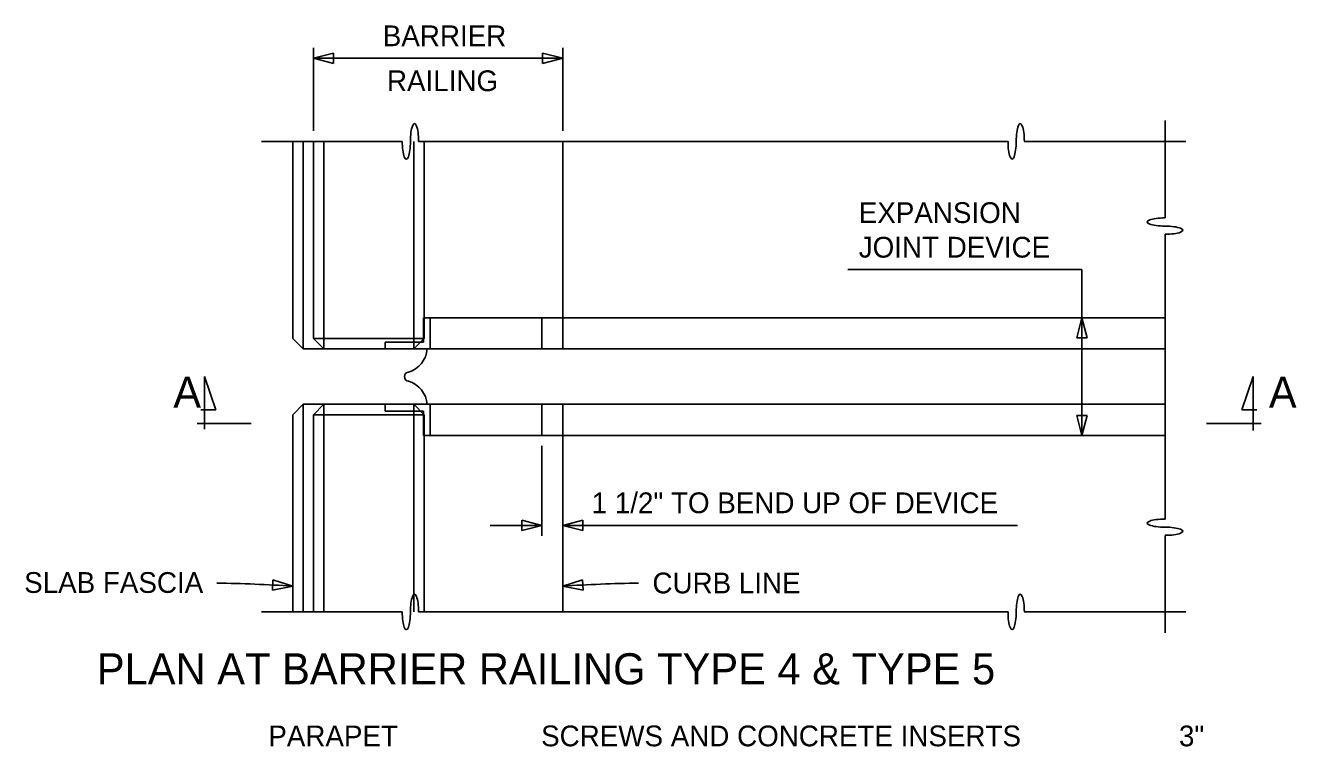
# Model space of a CAD drawing. Extents: x 19590 to 20151, y 19944 to 20103.
# Drawn here: x 19615.96 to 19644.51, y 20079.43 to 20095.63 of the extents above; entities that cross this region are included whole.
import ezdxf

# ---------------------------------------------------------------- set-up
doc = ezdxf.new("R2010")
doc.units = 0
for name, color, linetype in [('DETAIL_PR', 7, 'Continuous'), ('DETAIL_TEXT_DIMEN_PR', 7, 'Continuous'), ('Level 1', 7, 'Continuous')]:
    doc.layers.add(name, color=color, linetype=linetype)

msp = doc.modelspace()

# ---------------------------------------------------------------- linework, layer by layer
at = {"layer": 'DETAIL_PR'}
for p, q in [((19641.559, 20093.494), (19641.559, 20091.306)), ((19621.266, 20093.028), (19624.426, 20093.028)), ((19621.965, 20093.028), (19621.965, 20088.596)), ((19622.199, 20093.028), (19622.199, 20088.363)), ((19622.432, 20093.028), (19622.432, 20088.596)), ((19622.665, 20093.028), (19622.665, 20088.363)), ((19624.687, 20093.028), (19624.687, 20088.363)), ((19624.793, 20093.028), (19638.033, 20093.028)), ((19624.92, 20093.028), (19624.92, 20088.596)), ((19628.03, 20093.028), (19628.03, 20088.363)), ((19638.399, 20093.028), (19642.026, 20093.028)), ((19641.559, 20090.939), (19641.559, 20086.263)), ((19624.901, 20088.518), (19624.901, 20089.063)), ((19624.901, 20089.063), (19628.03, 20089.063)), ((19625.056, 20088.363), (19625.056, 20089.063)), ((19627.564, 20088.363), (19627.564, 20089.063)), ((19628.03, 20089.062), (19641.559, 20089.062)), ((19622.199, 20088.363), (19621.966, 20088.596)), ((19622.432, 20088.596), (19624.92, 20088.596)), ((19622.432, 20088.596), (19622.665, 20088.363)), ((19624.045, 20088.363), (19624.045, 20088.518)), ((19624.045, 20088.518), (19624.901, 20088.518)), ((19624.92, 20088.596), (19624.687, 20088.363)), ((19622.199, 20088.363), (19624.045, 20088.363)), ((19624.045, 20088.363), (19641.559, 20088.363)), ((19622.199, 20087.119), (19621.966, 20086.886)), ((19622.199, 20087.119), (19624.045, 20087.119)), ((19622.199, 20082.453), (19622.199, 20087.119)), ((19622.432, 20086.886), (19622.665, 20087.119)), ((19622.665, 20082.453), (19622.665, 20087.119)), ((19624.045, 20087.119), (19624.045, 20086.963)), ((19624.045, 20087.119), (19641.559, 20087.119)), ((19624.045, 20086.963), (19624.901, 20086.963)), ((19624.687, 20082.453), (19624.687, 20087.119)), ((19624.92, 20086.885), (19624.687, 20087.119)), ((19624.901, 20086.963), (19624.901, 20086.419)), ((19625.056, 20087.119), (19625.056, 20086.419)), ((19627.564, 20086.419), (19627.564, 20087.119)), ((19628.03, 20082.453), (19628.03, 20087.119)), ((19621.965, 20082.453), (19621.965, 20086.885)), ((19622.432, 20082.453), (19622.432, 20086.885)), ((19622.432, 20086.885), (19624.92, 20086.885)), ((19624.92, 20082.453), (19624.92, 20086.885)), ((19624.901, 20086.419), (19628.03, 20086.419)), ((19628.03, 20086.419), (19641.559, 20086.419)), ((19641.559, 20084.542), (19641.559, 20086.263)), ((19641.559, 20084.175), (19641.559, 20081.987)), ((19621.266, 20082.454), (19624.426, 20082.454)), ((19624.793, 20082.454), (19638.033, 20082.454)), ((19638.399, 20082.454), (19642.026, 20082.454))]:
    msp.add_line(p, q, dxfattribs=at)
for centre, radius, start, end in [((19624.374, 20088.428), 0.618, 288.1365, 353.9316), ((19624.574, 20087.741), 0.101, 94.4387, 265.5613), ((19624.374, 20087.053), 0.618, 6.0684, 71.8635)]:
    msp.add_arc(centre, radius, start, end, dxfattribs=at)
for centre, major_axis, ratio, start_param, end_param in [((19624.701, 20093.028), (0, -0.398), 0.230204, 1.570796, 4.712389), ((19638.308, 20093.028), (0, -0.398), 0.230204, 1.570796, 4.712389), ((19624.517, 20093.028), (0, -0.398), 0.230206, 4.712389, 7.853982), ((19638.124, 20093.028), (0, -0.398), 0.230206, 4.712389, 7.853982), ((19641.559, 20091.215), (0.398, 0), 0.230204, 1.570796, 4.712389), ((19641.559, 20091.031), (0.398, 0), 0.230206, 4.712389, 7.853982), ((19641.559, 20084.45), (0.398, 0), 0.230204, 1.570796, 4.712389), ((19641.559, 20084.267), (0.398, 0), 0.230206, 4.712389, 7.853982), ((19624.701, 20082.454), (0, -0.398), 0.230204, 1.570796, 4.712389), ((19638.308, 20082.454), (0, -0.398), 0.230204, 1.570796, 4.712389), ((19624.517, 20082.454), (0, -0.398), 0.230206, 4.712389, 7.853982), ((19638.124, 20082.454), (0, -0.398), 0.230206, 4.712389, 7.853982)]:
    msp.add_ellipse(centre, major_axis=major_axis, ratio=ratio, start_param=start_param, end_param=end_param, dxfattribs=at)
at = {"layer": 'DETAIL_TEXT_DIMEN_PR'}
for p, q in [((19622.432, 20093.261), (19622.432, 20095.127)), ((19622.884, 20095.011), (19622.432, 20094.894)), ((19622.884, 20094.777), (19622.884, 20095.011)), ((19627.579, 20095.011), (19628.03, 20094.894)), ((19627.579, 20094.777), (19627.579, 20095.011)), ((19628.03, 20093.261), (19628.03, 20095.127)), ((19622.432, 20094.894), (19628.03, 20094.894)), ((19622.432, 20094.894), (19622.884, 20094.777)), ((19628.03, 20094.894), (19627.579, 20094.777)), ((19634.436, 20090.151), (19639.693, 20090.151)), ((19639.693, 20090.151), (19639.693, 20086.419)), ((19619.984, 20086.56), (19619.983, 20087.741)), ((19619.983, 20087.741), (19620.238, 20086.998)), ((19643.542, 20087.741), (19643.287, 20086.998)), ((19643.541, 20086.532), (19643.542, 20087.741)), ((19620.238, 20086.998), (19619.905, 20086.998)), ((19643.287, 20086.998), (19643.62, 20086.998)), ((19621.032, 20086.691), (19619.816, 20086.691)), ((19642.492, 20086.691), (19643.718, 20086.691)), ((19627.564, 20084.164), (19627.564, 20086.186)), ((19626.397, 20084.397), (19627.564, 20084.397)), ((19628.03, 20084.397), (19638.242, 20084.397))]:
    msp.add_line(p, q, dxfattribs=at)
for centre, start, end in [((19619.518, 20043.619), 86.4465, 88.9222), ((19630.478, 20043.619), 91.0778, 93.5535)]:
    msp.add_arc(centre, 39.492, start, end, dxfattribs=at)
at = {"layer": 'Level 1'}
for p, q in [((19639.693, 20089.062), (19639.577, 20088.611)), ((19639.81, 20088.611), (19639.693, 20089.062)), ((19639.577, 20088.611), (19639.81, 20088.611)), ((19639.81, 20086.871), (19639.576, 20086.871)), ((19639.576, 20086.871), (19639.693, 20086.419)), ((19639.693, 20086.419), (19639.81, 20086.871)), ((19627.112, 20084.281), (19627.112, 20084.514)), ((19627.112, 20084.514), (19627.564, 20084.397)), ((19627.564, 20084.397), (19627.112, 20084.281)), ((19628.482, 20084.514), (19628.03, 20084.397)), ((19628.03, 20084.397), (19628.482, 20084.281)), ((19628.482, 20084.281), (19628.482, 20084.514)), ((19621.508, 20082.943), (19621.521, 20083.176)), ((19621.965, 20083.035), (19621.508, 20082.943)), ((19621.521, 20083.176), (19621.965, 20083.035)), ((19628.475, 20083.176), (19628.03, 20083.035)), ((19628.03, 20083.035), (19628.488, 20082.943)), ((19628.488, 20082.943), (19628.475, 20083.176))]:
    msp.add_line(p, q, dxfattribs=at)

# ---------------------------------------------------------------- texts
at = {"layer": 'DETAIL_TEXT_DIMEN_PR'}
for s, height, p in [('BARRIER', 0.4665, (19623.989, 20095.166)), ('RAILING', 0.4665, (19624.082, 20094.156)), ('EXPANSION ', 0.4665, (19634.68, 20091.193)), ('JOINT DEVICE', 0.46652, (19634.68, 20090.416)), ('A', 0.7, (19619.283, 20087.041)), ('A', 0.7, (19643.892, 20087.041)), ('1 1/2" TO BEND UP OF DEVICE', 0.46652, (19628.68, 20084.673)), ('SLAB FASCIA', 0.46652, (19615.933, 20082.882)), ('CURB LINE', 0.4665, (19630.046, 20082.871)), ('PLAN AT BARRIER RAILING TYPE 4 & TYPE 5', 0.69987, (19617.565, 20080.826)), ('PARAPET', 0.4665, (19621.417, 20079.435)), ('SCREWS AND CONCRETE INSERTS', 0.46652, (19627.545, 20079.435)), ('3"', 0.4665, (19641.872, 20079.435))]:
    msp.add_text(s, height=height, dxfattribs=at).set_placement(p)

doc.saveas('drawing.dxf')
